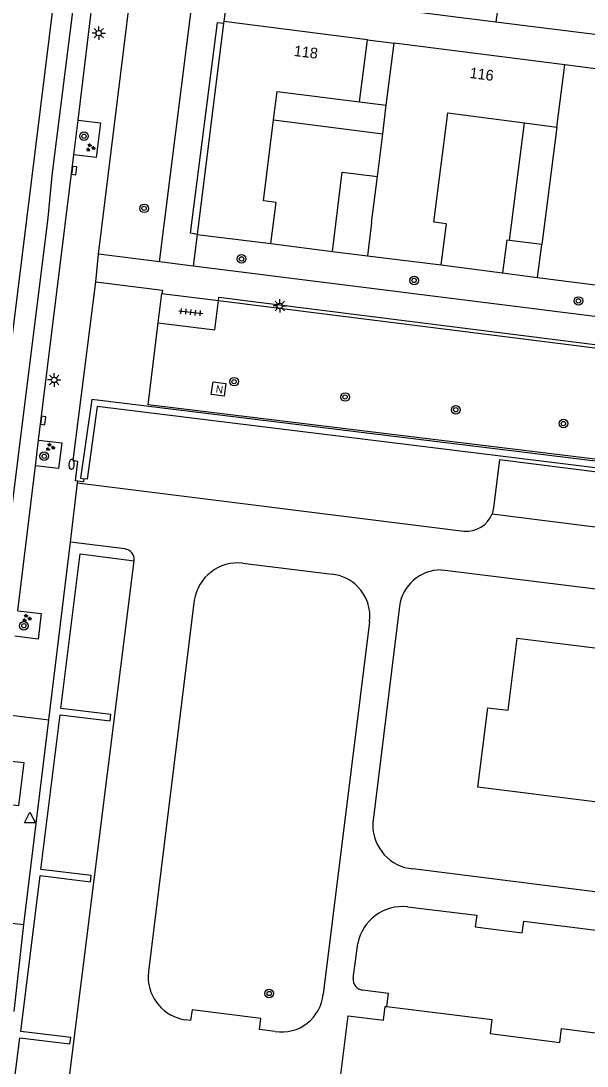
# Model space of a CAD drawing. Extents: x 131000 to 133014, y 396499 to 399001.
# Drawn here: x 131618.1 to 131670.9, y 396614.9 to 396712.4 of the extents above; entities that cross this region are included whole.
import ezdxf

# ---------------------------------------------------------------- set-up
doc = ezdxf.new("R2010")
doc.units = 0
for name, color, linetype in [('gg-afsc-erfafscheiding', 7, 'Continuous'), ('gg-afsc-hekwerk', 7, 'Continuous'), ('gg-afsc-muur', 7, 'Continuous'), ('gg-anno-huisnummerreeks BGT', 7, 'Continuous'), ('gg-bbg-bijgebouw', 7, 'Continuous'), ('gg-bbg-gedigitaliseerde bebouwing', 7, 'Continuous'), ('gg-bbg-gedigitaliseerde bijgebouw', 7, 'Continuous'), ('gg-bbg-hoofdgebouw', 7, 'Continuous'), ('gg-bbg-luifel en loopbrug', 7, 'Continuous'), ('gg-bbg-tussenscheiding', 7, 'Continuous'), ('gg-knt-verharding', 7, 'Continuous'), ('gg-knt-verharding nz', 7, 'Continuous'), ('gt-grn-groengrens', 7, 'Continuous'), ('gt-grn-weggrens', 7, 'Continuous'), ('gt-symb-boom', 7, 'Continuous'), ('gt-symb-brandkraan', 7, 'Continuous'), ('gt-symb-groenvak', 7, 'Continuous'), ('gt-symb-kolk', 7, 'Continuous'), ('gt-symb-lichtmast', 7, 'Continuous'), ('gt-symb-nortonput', 7, 'Continuous'), ('gt-symb-tegel verharding', 7, 'Continuous'), ('gt-symb-waterafsluiter', 7, 'Continuous')]:
    doc.layers.add(name, color=color, linetype=linetype)

# ---------------------------------------------------------------- blocks, each defined once
blk = doc.blocks.new('gt0-BOOM')
at = {"layer": 'gt-symb-boom'}
for radius in [0.4, 0.2]:
    blk.add_circle((0, 0), radius, dxfattribs=at)
blk = doc.blocks.new('gt0-KOLK')
at = {"layer": 'gt-symb-kolk'}
blk.add_lwpolyline([(0, 0), (0.375, 0), (0.375, 0.4), (-0.375, 0.4), (-0.375, 0), (0, 0)], dxfattribs=at)
blk = doc.blocks.new('gt0-GRVAK')
at = {"layer": 'gt-symb-groenvak'}
for p, q in [((-0.11, 0.189), (-0.228, 0.24)), ((-0.182, 0.153), (0.088, 0.153)), ((-0.091, 0.211), (-0.156, 0.322)), ((-0.047, 0.214), (-0.047, 0.393)), ((-0.004, 0.211), (0.061, 0.322)), ((0.015, 0.189), (0.133, 0.24)), ((0.262, -0.052), (0.197, 0.059)), ((0.305, -0.049), (0.305, 0.13)), ((0.349, -0.052), (0.414, 0.059)), ((-0.245, -0.228), (-0.363, -0.177)), ((-0.318, -0.264), (-0.047, -0.264)), ((-0.226, -0.206), (-0.291, -0.095)), ((-0.183, -0.203), (-0.183, -0.024)), ((-0.139, -0.206), (-0.074, -0.095)), ((-0.12, -0.228), (-0.002, -0.177)), ((0.243, -0.074), (0.125, -0.023)), ((0.17, -0.11), (0.441, -0.11)), ((0.368, -0.074), (0.486, -0.023))]:
    blk.add_line(p, q, dxfattribs=at)
blk = doc.blocks.new('gt0-LMAST')
at = {"layer": 'gt-symb-lichtmast'}
for p, q in [((-0.182, 0.173), (-0.447, 0.438)), ((-0.005, 0.246), (-0.005, 0.621)), ((0.172, 0.173), (0.437, 0.438)), ((-0.255, -0.004), (-0.63, -0.004)), ((-0.182, -0.181), (-0.447, -0.446)), ((-0.005, -0.254), (-0.005, -0.629)), ((0.437, -0.446), (0.172, -0.181)), ((0.245, -0.004), (0.62, -0.004))]:
    blk.add_line(p, q, dxfattribs=at)
blk.add_circle((-0.005, -0.004), 0.25, dxfattribs=at)
blk = doc.blocks.new('gt0-BR')
at = {"layer": 'gt-symb-brandkraan'}
for centre, radius, start, end in [((-0.244, 0), 0.206, 107.56694, 252.43307), ((0.599, -2.664), 3, 106.89205, 107.56694), ((0, -0.691), 0.938, 73.10799, 106.89205), ((-0.599, -2.664), 3, 72.43309, 73.10799), ((0.244, 0), 0.206, 287.56695, 72.43309), ((0.599, 2.664), 3, 252.43307, 253.10797), ((0, 0.691), 0.938, 253.10797, 286.89206), ((-0.599, 2.664), 3, 286.89206, 287.56695)]:
    blk.add_arc(centre, radius, start, end, dxfattribs=at)
blk = doc.blocks.new('gt0-NPUT')
at = {"layer": 'gt-symb-nortonput'}
blk.add_lwpolyline([(-0.566, -0.608), (-0.566, 0.592), (0.634, 0.592), (0.634, -0.608)], close=True, dxfattribs=at)
blk.add_text('N', height=0.7, dxfattribs=at).set_placement((-0.221, -0.381))
blk = doc.blocks.new('gt0-TEG1')
at = {"layer": 'gt-symb-tegel verharding'}
for p, q in [((-1.125, 0), (1.125, 0)), ((-0.9, -0.25), (-0.9, 0.25)), ((-0.45, -0.25), (-0.45, 0.25)), ((0, -0.25), (0, 0.25)), ((0.45, -0.25), (0.45, 0.25)), ((0.9, -0.25), (0.9, 0.25))]:
    blk.add_line(p, q, dxfattribs=at)
blk = doc.blocks.new('gt0-WAFSL')
at = {"layer": 'gt-symb-waterafsluiter'}
for p, q in [((-0.5, -0.333), (0, 0.667)), ((0, 0.667), (0.5, -0.333)), ((0.5, -0.333), (-0.5, -0.333))]:
    blk.add_line(p, q, dxfattribs=at)

msp = doc.modelspace()

# ---------------------------------------------------------------- linework, layer by layer
at = {"layer": 'gg-afsc-erfafscheiding'}
msp.add_line((131657.33, 396689.63), (131663.05, 396688.89), dxfattribs=at)
at = {"layer": 'gg-afsc-hekwerk'}
for p, q in [((131630.943, 396684.217), (131631.287, 396686.968)), ((131631.287, 396686.968), (131636.551, 396686.309)), ((131636.551, 396686.309), (131714.442, 396676.549))]:
    msp.add_line(p, q, dxfattribs=at)
msp.add_lwpolyline([(131716.394, 396666.081), (131629.988, 396676.579), (131630.943, 396684.217)], dxfattribs=at)
at = {"layer": 'gg-afsc-muur'}
msp.add_line((131641.45, 396691.62), (131647.18, 396690.9), dxfattribs=at)
at = {"layer": 'gg-bbg-bijgebouw'}
for p, q in [((131666.7, 396691.53), (131663.676, 396691.92)), ((131647.18, 396690.9), (131650.436, 396690.493)), ((131663.05, 396688.89), (131666.307, 396688.469))]:
    msp.add_line(p, q, dxfattribs=at)
msp.add_lwpolyline([(131663.676, 396691.92), (131663.44, 396691.95), (131663.05, 396688.89)], dxfattribs=at)
at = {"layer": 'gg-bbg-gedigitaliseerde bebouwing'}
for p, q in [((131651.864, 396701.858), (131652.2, 396704.53)), ((131651.366, 396697.895), (131651.864, 396701.858))]:
    msp.add_line(p, q, dxfattribs=at)
at = {"layer": 'gg-bbg-gedigitaliseerde bijgebouw'}
msp.add_lwpolyline([(131647.18, 396690.9), (131648.099, 396698.3), (131651.366, 396697.895)], dxfattribs=at)
at = {"layer": 'gg-bbg-hoofdgebouw'}
for p, q in [((131637.031, 396712.187), (131634.56, 396692.48)), ((131637.05, 396712.34), (131637.031, 396712.187)), ((131650.447, 396710.636), (131637.05, 396712.34)), ((131649.71, 396704.841), (131650.447, 396710.636)), ((131652.2, 396704.53), (131652.928, 396710.321)), ((131668.855, 396708.295), (131652.928, 396710.321)), ((131682.217, 396706.596), (131668.855, 396708.295)), ((131665.076, 396702.891), (131668.11, 396702.5)), ((131668.11, 396702.5), (131666.7, 396691.53)), ((131634.56, 396692.48), (131641.45, 396691.62)), ((131650.436, 396690.493), (131657.33, 396689.63)), ((131666.307, 396688.469), (131673.18, 396687.58))]:
    msp.add_line(p, q, dxfattribs=at)
for points in [[(131641.688, 396703.157), (131642.02, 396705.8), (131649.71, 396704.841)], [(131641.45, 396691.62), (131641.94, 396695.47), (131640.74, 396695.62), (131641.688, 396703.157)], [(131657.33, 396689.63), (131657.82, 396693.48), (131656.62, 396693.63), (131657.94, 396703.81), (131665.076, 396702.891)], [(131688.242, 396638.476), (131682.177, 396639.229), (131682.047, 396638.247), (131660.733, 396640.905), (131661.665, 396648.326), (131663.572, 396648.103), (131664.4, 396654.813), (131672.644, 396653.786), (131672.913, 396655.766), (131693.428, 396653.219), (131693.794, 396656.181), (131705.394, 396654.74), (131705.029, 396651.776), (131735.772, 396647.917), (131735.529, 396645.937), (131738.21, 396645.602), (131735.868, 396626.792), (131722.139, 396628.503), (131722.709, 396633.163), (131712.377, 396634.461), (131712.502, 396635.466), (131706.49, 396636.212)], [(131647.76, 396612.365), (131648.65, 396619.581), (131651.926, 396619.182), (131652.087, 396620.456), (131652.252, 396620.436)], [(131652.252, 396620.436), (131662.051, 396619.229), (131661.892, 396617.939), (131668.393, 396617.103), (131668.536, 396618.398), (131678.507, 396617.13), (131678.342, 396615.83), (131684.854, 396615.032), (131685.011, 396616.319), (131694.979, 396615.082), (131694.818, 396613.782), (131701.335, 396612.958), (131701.492, 396614.25), (131711.235, 396613.032)]]:
    msp.add_lwpolyline(points, dxfattribs=at)
at = {"layer": 'gg-bbg-luifel en loopbrug'}
for p, q in [((131650.447, 396710.636), (131652.928, 396710.321)), ((131649.71, 396704.841), (131652.2, 396704.53)), ((131641.688, 396703.157), (131651.864, 396701.858)), ((131663.676, 396691.92), (131665.076, 396702.891))]:
    msp.add_line(p, q, dxfattribs=at)
at = {"layer": 'gg-bbg-tussenscheiding'}
for p, q in [((131668.11, 396702.5), (131668.855, 396708.295)), ((131650.82, 396693.55), (131651.366, 396697.895)), ((131650.82, 396693.55), (131650.436, 396690.493)), ((131666.307, 396688.469), (131666.7, 396691.53))]:
    msp.add_line(p, q, dxfattribs=at)
at = {"layer": 'gg-knt-verharding'}
for p, q in [((131625.361, 396690.639), (131630.463, 396731.888)), ((131637.43, 396715.47), (131662.423, 396712.313)), ((131623.472, 396703.134), (131624.776, 396713.947)), ((131662.423, 396712.313), (131685.321, 396709.421)), ((131623.081, 396699.892), (131623.472, 396703.134)), ((131619.788, 396673.286), (131623.081, 396699.892)), ((131631.053, 396689.923), (131625.361, 396690.639)), ((131634.188, 396689.528), (131631.053, 396689.923)), ((131717.638, 396679.02), (131634.188, 396689.528)), ((131625.125, 396688.058), (131631.326, 396687.278)), ((131631.326, 396687.278), (131631.287, 396686.968)), ((131636.551, 396686.309), (131636.588, 396686.616)), ((131636.588, 396686.616), (131714.476, 396676.821)), ((131619.498, 396670.904), (131619.788, 396673.286)), ((131617.852, 396657.368), (131619.498, 396670.904)), ((131622.754, 396663.784), (131623.425, 396669.294)), ((131623.425, 396669.294), (131623.445, 396669.454)), ((131623.425, 396669.294), (131659.428, 396664.787)), ((131623.904, 396669.394), (131623.445, 396669.454)), ((131623.962, 396669.386), (131623.904, 396669.394)), ((131620.733, 396647.196), (131622.754, 396663.784)), ((131627.813, 396663.135), (131622.754, 396663.784)), ((131638.817, 396661.812), (131647.141, 396660.773)), ((131650.633, 396656.338), (131646.31, 396621.595)), ((131618.405, 396628.085), (131620.733, 396647.196)), ((131744.94, 396621.918), (131654.681, 396633.285)), ((131617.508, 396619.995), (131618.405, 396628.085)), ((131649.109, 396623.09), (131649.533, 396626.334))]:
    msp.add_line(p, q, dxfattribs=at)
for points in [[(131634.56, 396692.48), (131633.958, 396692.589), (131636.472, 396712.257), (131637.031, 396712.187)], [(131623.472, 396703.134), (131625.565, 396702.882), (131625.155, 396699.642), (131623.081, 396699.892)], [(131623.445, 396669.454), (131623.22, 396669.484), (131623.457, 396671.302), (131622.997, 396671.384), (131625.125, 396688.058)], [(131630.943, 396684.217), (131636.218, 396683.575), (131636.551, 396686.309)], [(131619.788, 396673.286), (131621.941, 396673.026), (131621.654, 396670.644), (131619.498, 396670.904)], [(131688.127, 396664.006), (131688.605, 396668.194), (131662.747, 396671.441), (131662.205, 396666.994), (131662.143, 396666.695), (131662.059, 396666.413)], [(131617.383, 396571.775), (131612.335, 396572.434), (131614.219, 396587.296), (131618.858, 396586.639), (131618.944, 396587.297), (131614.276, 396587.872), (131616.108, 396602.429), (131620.79, 396601.838), (131620.862, 396602.437), (131616.186, 396603.005), (131618.042, 396617.519), (131622.708, 396616.958), (131622.779, 396617.549), (131618.119, 396618.104), (131619.929, 396632.671), (131624.616, 396632.088), (131624.674, 396632.658), (131619.994, 396633.238), (131621.801, 396647.67), (131626.466, 396647.115), (131626.524, 396647.698), (131621.865, 396648.266), (131623.667, 396662.67), (131628.697, 396662.026)], [(131657.307, 396661.181), (131657.658, 396661.166), (131691.584, 396656.959), (131691.726, 396658.009)], [(131634.292, 396658.345), (131630.02, 396623.727), (131629.991, 396623.239)], [(131617.852, 396657.368), (131620.018, 396657.107), (131619.73, 396654.724), (131617.562, 396654.986)], [(131653.435, 396657.804), (131650.944, 396637.58), (131650.94, 396637.39)], [(131615.713, 396639.461), (131617.932, 396639.204), (131618.453, 396643.171), (131616.217, 396643.394)], [(131654.181, 396629.753), (131660.632, 396628.973), (131660.5, 396627.881), (131664.872, 396627.313), (131665.021, 396628.412), (131700.733, 396623.957), (131700.579, 396622.835), (131705.049, 396622.283), (131705.195, 396623.382), (131711.639, 396622.579)], [(131652.252, 396620.436), (131652.409, 396621.66), (131649.977, 396621.983)], [(131641.851, 396618.123), (131640.375, 396618.308), (131640.496, 396619.318), (131634.096, 396620.138), (131633.961, 396619.144), (131633.474, 396619.203)]]:
    msp.add_lwpolyline(points, dxfattribs=at)
for centre, radius, start, end in [((131659.672, 396667.335), 2.559, 264.53921, 338.89424), ((131627.692, 396662.132), 1.01, 353.98476, 83.13295), ((131638.372, 396657.706), 4.13, 83.81271, 171.10509), ((131657.311, 396657.268), 3.913, 90.05627, 172.13094), ((131646.754, 396656.883), 3.909, 44.93127, 84.31224), ((131646.751, 396656.872), 3.918, 352.16179, 45.01978), ((131655.061, 396637.389), 4.121, 179.98464, 264.70292), ((131653.749, 396625.471), 4.304, 84.24152, 168.43378), ((131634.07, 396623.238), 4.079, 179.98484, 261.60244), ((131650.109, 396622.98), 1.006, 173.73949, 262.46058), ((131642.451, 396621.952), 3.876, 261.09489, 354.71732)]:
    msp.add_arc(centre, radius, start, end, dxfattribs=at)
at = {"layer": 'gg-knt-verharding nz'}
for p, q in [((131662.059, 396666.413), (131689.013, 396662.998)), ((131617.383, 396571.775), (131628.697, 396662.026)), ((131616.716, 396647.689), (131620.733, 396647.196)), ((131614.322, 396628.584), (131618.405, 396628.085))]:
    msp.add_line(p, q, dxfattribs=at)
for points in [[(131621.21, 396714.486), (131613.112, 396649.429), (131611.053, 396633.823), (131609.539, 396621.529), (131609.081, 396615.245), (131609.081, 396608.501), (131608.978, 396605.027)], [(131623.062, 396714.253), (131621.03, 396697.981), (131620.634, 396694.035), (131615.013, 396649.177), (131612.475, 396628.502), (131611.696, 396622.63), (131611.237, 396617.722), (131611.053, 396611.896), (131611.007, 396606.758), (131611.14, 396602.782)]]:
    msp.add_lwpolyline(points, dxfattribs=at)
at = {"layer": 'gt-grn-groengrens'}
for p, q in [((131637.43, 396715.47), (131637.05, 396712.34)), ((131634.56, 396692.48), (131634.188, 396689.528)), ((131624.001, 396669.688), (131623.962, 396669.386))]:
    msp.add_line(p, q, dxfattribs=at)
for points in [[(131631.053, 396689.923), (131634.616, 396718.361), (131637.69, 396717.97)], [(131716.366, 396665.85), (131624.733, 396677.094), (131623.704, 396669.727), (131624.001, 396669.688)], [(131750.18, 396661.044), (131625.245, 396676.426), (131624.298, 396669.649), (131624.001, 396669.688)]]:
    msp.add_lwpolyline(points, dxfattribs=at)
at = {"layer": 'gt-grn-weggrens'}
for p, q in [((131662.709, 396714.554), (131662.423, 396712.313)), ((131625.125, 396688.058), (131625.361, 396690.639))]:
    msp.add_line(p, q, dxfattribs=at)

# ---------------------------------------------------------------- block references
at = {"layer": 'gt-symb-boom'}
for p in [(131624.017, 396701.642), (131638.704, 396690.2), (131654.794, 396688.188), (131670.11, 396686.272), (131638.008, 396678.744), (131648.361, 396677.311), (131658.681, 396676.119), (131668.719, 396674.837), (131620.308, 396671.784), (131618.417, 396655.97), (131641.288, 396621.663)]:
    msp.add_blockref('gt0-BOOM', p, dxfattribs=at)
at = {"layer": 'gt-symb-boom', "rotation": 90}
msp.add_blockref('gt0-BOOM', (131629.622, 396694.913), dxfattribs=at)
at = {"layer": 'gt-symb-brandkraan', "rotation": 84.95083353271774}
msp.add_blockref('gt0-BR', (131622.861, 396671.028), dxfattribs=at)
at = {"layer": 'gt-symb-groenvak'}
for p in [(131624.603, 396700.579), (131620.851, 396672.632), (131618.665, 396656.674)]:
    msp.add_blockref('gt0-GRVAK', p, dxfattribs=at)
at = {"layer": 'gt-symb-kolk'}
for p, rotation in [((131622.908, 396698.46), -97.06814005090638), ((131620.014, 396675.147), -96.94741065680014)]:
    msp.add_blockref('gt0-KOLK', p, dxfattribs=dict(at, rotation=rotation))
at = {"layer": 'gt-symb-lichtmast'}
for p in [(131625.398, 396711.263), (131642.272, 396685.811), (131621.249, 396678.905)]:
    msp.add_blockref('gt0-LMAST', p, dxfattribs=at)
at = {"layer": 'gt-symb-nortonput', "rotation": -8.340866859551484}
msp.add_blockref('gt0-NPUT', (131636.535, 396678.071), dxfattribs=at)
at = {"layer": 'gt-symb-tegel verharding', "rotation": -6.314884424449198}
msp.add_blockref('gt0-TEG1', (131633.972, 396685.229), dxfattribs=at)
at = {"layer": 'gt-symb-waterafsluiter'}
msp.add_blockref('gt0-WAFSL', (131618.98, 396637.903), dxfattribs=at)

# ---------------------------------------------------------------- texts
at = {"layer": 'gg-anno-huisnummerreeks BGT'}
for s, rotation, p in [('118', 352.9, (131643.542, 396709.137)), ('116', 352.6, (131659.932, 396707.083))]:
    msp.add_text(s, height=1, rotation=rotation, dxfattribs=at).set_placement(p)

doc.saveas('drawing.dxf')
